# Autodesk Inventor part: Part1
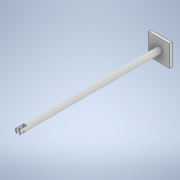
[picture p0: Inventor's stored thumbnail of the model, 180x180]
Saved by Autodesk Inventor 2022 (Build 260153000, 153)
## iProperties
Created: 2021-07
Part Number: Part1
Material: Generic
Document SubType Name: Modeling
Designer: Hp
Density: 1 g/cm^3
Appearance: Default
Author: Hp
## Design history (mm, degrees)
sketch "Sketch1"
  geometry: C1 r 40 at (0, 0); 1 further point
  constraints: 1 centre point, 1 coincident
  dimensions: "d0" = 80 diameter of C1
extrude "Extrusion1" new body sketch "Sketch1" distance "d1" = 2000; taper "d2" = 0 deg
sketch "Sketch2"
  geometry: L1 (22.5, -56.066)-(-22.5, -56.066); L2 (-22.5, -56.066)-(-22.5, 56.066); L3 (-22.5, 56.066)-(22.5, 56.066); L4 (22.5, 56.066)-(22.5, -56.066); L5 (22.5, -56.066)-(-22.5, 56.066); L6 (-22.5, -56.066)-(22.5, 56.066); 1 further point
  constraints: 12 end point, 2 midpoint, 2 parallel, 1 horizontal, 1 perpendicular
  dimensions: "d3" = 45 distance between parallel lines of L4 L2
extrude "Extrusion2" cut sketch "Sketch2" distance "d4" = 100; taper "d5" = 0 deg
sketch "Sketch3"
  geometry: C1 r 10 at (0, 1960); 1 further point
  constraints: 1 centre point
  dimensions: "d6" = 20 diameter of C1
extrude "Extrusion3" cut sketch "Sketch3" extent not by distance; stored distance "d7" = 0; taper "d8" = 0 deg
sketch "Sketch4"
  geometry: L1 (150, -150)-(-150, -150); L2 (-150, -150)-(-150, 150); L3 (-150, 150)-(150, 150); L4 (150, 150)-(150, -150); L5 (150, -150)-(-150, 150); L6 (-150, -150)-(150, 150); 1 further point
  constraints: 12 end point, 2 midpoint, 2 parallel, 1 horizontal, 1 perpendicular
  dimensions: "d9" = 300 distance of L2.end L3.end; "d10" = 300 distance of L1.end L2.end
extrude "Extrusion4" join sketch "Sketch4" distance "d11" = 40; taper "d12" = 0 deg
sketch "Sketch5"
  geometry: 1 further point
body "Solid1"
